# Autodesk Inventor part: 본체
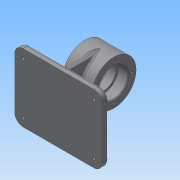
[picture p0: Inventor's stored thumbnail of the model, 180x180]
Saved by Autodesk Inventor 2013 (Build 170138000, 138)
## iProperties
Created: 2019-09
Part Number: 본체
Material: 일반
Document SubType Name: Modeling
Designer: Administrator
Density: 1 g/cm^3
Author: Administrator
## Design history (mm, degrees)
sketch "스케치1"
  geometry: L1 (-21, 0)-(21, 0); L2 (-21, 0)-(-21, 32); L3 (-21, 32)-(21, 32); L4 (21, 32)-(21, 0); L5 (-21, 21)-(-6, 21); L6 (-6, 21)-(-6, 18); L7 (-6, 18)-(6, 18); L8 (6, 18)-(6, 21); L9 (6, 21)-(21, 21); L10 (-63, -50)-(63, -50); L11 (63, -50)-(63, -59); L12 (63, -59)-(-63, -59); L13 (-63, -59)-(-63, -50); 3 further points
  constraints: 26 end point, 6 perpendicular, 5 parallel, 2 coincident, 2 equal length, 2 horizontal, 2 midpoint, 2 point on line, 1 vertical alignment
  dimensions: "d0" = 64 diameter of L3 L1; "d2" = 42 diameter of L9 L1; "d3" = 36 diameter of L7 L1; "d4" = 15 distance of L5.start L5.end; "d5" = 42 distance of L2.end L3.end; "d6" = 9 distance of L10.end L11.end; "d7" = 59 distance from line of point (0, 0) L12; "d8" = 126 distance of L11.end L12.end
revolve "회전1" stored, may be unused: angle "d9" = 90 deg
extrude "돌출1" join sketch "스케치1" distance "d10" = 36; taper "d12" = 0 deg; dims "d11" = 62, "d13" = 0
sketch "스케치4"
  geometry: L1 (59, 68)-(67, 68); L2 (67, 68)-(67, 4); L3 (67, 4)-(59, 4); L4 (59, 4)-(59, 68); L5 (46, 40)-(80, 40); L6 (80, 40)-(80, 32); L7 (80, 32)-(46, 32); L8 (46, 32)-(46, 40); 5 further points
  constraints: 16 end point, 4 midpoint, 4 parallel, 2 horizontal, 2 horizontal alignment, 2 perpendicular, 2 vertical alignment
  dimensions: "d14" = 8 distance of L1.start L1.end; "d16" = 64 distance of L1.end L2.end; "d17" = 8 distance of L5.end L6.end; "d18" = 34 distance of L6.end L7.end
extrude "돌출2" join sketch "스케치4" stored distance "d19" = 36; taper "d20" = 0 deg
sketch "스케치5"
  geometry: C1 r 32 at (0, 0) reference; 1 further point
  constraints: 1 vertical alignment
  dimensions: "d21" = 26 distance of C1.centre point (0, 26)
hole "구멍1" sketch "스케치5" at (0, 26) diameter "d22" = 3.242; stored, may be unused: countersink angle "d26" = 90 deg, drill point angle "d28" = 118 deg; dims "d23" = 8, "d24" = 4, "d25" = 2, "d27" = 10
chamfer "모따기1" distance "d32" = 1; stored, may be unused: second distance "d33" = 2, angle "d34" = 45 deg
fillet "모깎기1" dims "d35" = 0.3
fillet "모깎기2" dims "d36" = 12
sketch "스케치6"
  geometry: A1 r 12 centre (0, 12) between (-12, 12) and (0, 0) reference; A2 r 12 centre (102, 12) between (102, 0) and (114, 12) reference; A3 r 12 centre (102, 86) between (114, 86) and (102, 98) reference; A4 r 12 centre (0, 86) between (0, 98) and (-12, 86) reference; 5 further points
  constraints: 4 coincident
hole "구멍2" sketch "스케치6" at (0, 12), (0, 86), (102, 86), (102, 12) diameter "d37" = 4.5; stored, may be unused: countersink angle "d41" = 90 deg, drill point angle "d43" = 118 deg; dims "d38" = 8, "d39" = 8, "d40" = 4.4, "d42" = 10
sketch "스케치7"
  geometry: L1 (114, 12)-(114, 86) reference; L2 (0, 98)-(102, 98) reference; 2 further points
  constraints: 1 other
  dimensions: "d44" = 63 distance from line of point (51, 88) L1; "d45" = 10 distance from line of point (51, 88) L2
feature "엠보싱1" sketch "스케치7" dims "d0" = 64, "d2" = 42, "d3" = 36, "d4" = 15, "d5" = 42, "d6" = 9, "d7" = 59, "d8" = 126, "d46" = 0.5, "d47" = 0
fillet "모깎기3" dims "d48" = 3
fillet "모깎기4" dims "d49" = 3
fillet "모깎기5" dims "d50" = 3
node "솔리드1"
pattern_circular "원형 패턴1" dims angle "d30" = 360 deg
mirror "대칭1"
